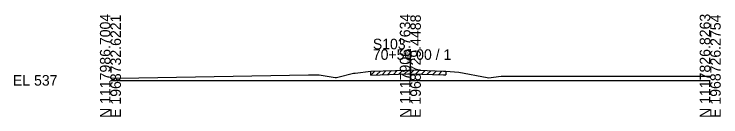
# Model space of a CAD drawing. Extents: x -26 to 163, y -10 to 45020.
# Drawn here: x -25.7 to 162.8, y 29490.3 to 29517.6 of the extents above; entities that cross this region are included whole.
import ezdxf

# ---------------------------------------------------------------- set-up
doc = ezdxf.new("R2010")
doc.units = 0
for name, color, linetype in [('RD_GPK_XS_Cell', 7, 'Continuous'), ('RD_XS_ExGround', 7, 'Continuous'), ('RD_XS_ExPaveRet', 7, 'Continuous'), ('RD_XS_TX_Elev_EX', 7, 'Continuous')]:
    doc.layers.add(name, color=color, linetype=linetype)

msp = doc.modelspace()

# ---------------------------------------------------------------- linework, layer by layer
at = {"layer": 'RD_GPK_XS_Cell'}
for p, q in [((80, 29500), (80, 29508.25)), ((0, 29500), (80, 29500)), ((80, 29500), (160, 29500))]:
    msp.add_line(p, q, dxfattribs=at)
at = {"layer": 'RD_XS_ExGround'}
for p, q in [((60.64, 29500.81), (64.88, 29501.9)), ((64.88, 29501.9), (65.26, 29501.94)), ((65.26, 29501.94), (69.47, 29502.4)), ((69.47, 29502.4), (79.32, 29502.72)), ((79.32, 29502.72), (80.17, 29502.75)), ((80.17, 29502.75), (88.83, 29502.45)), ((88.83, 29502.45), (89.47, 29502.42)), ((89.47, 29502.42), (92.95, 29502.18)), ((92.95, 29502.18), (100.46, 29500.73)), ((0, 29500.58), (7.58, 29500.65)), ((7.58, 29500.65), (52.81, 29501.42)), ((52.81, 29501.42), (55.72, 29501.46)), ((55.72, 29501.46), (59.94, 29500.78)), ((59.94, 29500.78), (60.31, 29500.72)), ((60.31, 29500.72), (60.64, 29500.81)), ((100.46, 29500.73), (100.81, 29500.66)), ((100.81, 29500.66), (104.19, 29501.13)), ((104.19, 29501.13), (105.12, 29501.09)), ((105.12, 29501.09), (107.83, 29501.12)), ((107.83, 29501.12), (160, 29501.1))]:
    msp.add_line(p, q, dxfattribs=at)
at = {"layer": 'RD_XS_ExPaveRet'}
for p, q in [((69.47, 29501.4), (70.5, 29502.43)), ((69.47, 29501.4), (69.47, 29502.4)), ((69.47, 29501.4), (79.32, 29501.72)), ((70.97, 29501.45), (72, 29502.48)), ((72.47, 29501.5), (73.5, 29502.53)), ((73.97, 29501.54), (75, 29502.58)), ((75.47, 29501.59), (76.5, 29502.63)), ((76.97, 29501.64), (78, 29502.68)), ((78.47, 29501.69), (79.5, 29502.73)), ((79.32, 29501.72), (80.17, 29501.75)), ((79.97, 29501.74), (80.95, 29502.72)), ((80.17, 29501.75), (88.83, 29501.45)), ((81.47, 29501.7), (82.44, 29502.67)), ((82.97, 29501.65), (83.94, 29502.62)), ((84.47, 29501.6), (85.44, 29502.57)), ((85.97, 29501.55), (86.94, 29502.51)), ((87.47, 29501.49), (88.44, 29502.46)), ((89.47, 29502.42), (89.47, 29501.42)), ((88.83, 29501.45), (89.47, 29501.42))]:
    msp.add_line(p, q, dxfattribs=at)

# ---------------------------------------------------------------- texts
at = {"layer": 'RD_GPK_XS_Cell'}
for s, p in [('N 1117986.7004', (0, 29490)), ('E 1968732.6221', (2.8, 29490)), ('N 1117906.7634', (80, 29490)), ('E 1968729.4488', (82.8, 29490)), ('N 1117826.8263', (160, 29490)), ('E 1968726.2754', (162.8, 29490))]:
    msp.add_text(s, height=2.8, rotation=90, dxfattribs=at).set_placement(p)
for s, p in [('S103', (70, 29508.25)), ('70+50.00 / 1', (70, 29505.45)), ('EL 537', (-26, 29498.6))]:
    msp.add_text(s, height=2.8, dxfattribs=at).set_placement(p)
at = {"layer": 'RD_XS_TX_Elev_EX'}
msp.add_text('539.74', height=0.8, rotation=90, dxfattribs=at).set_placement((79.9, 29504.74))

doc.saveas('drawing.dxf')
